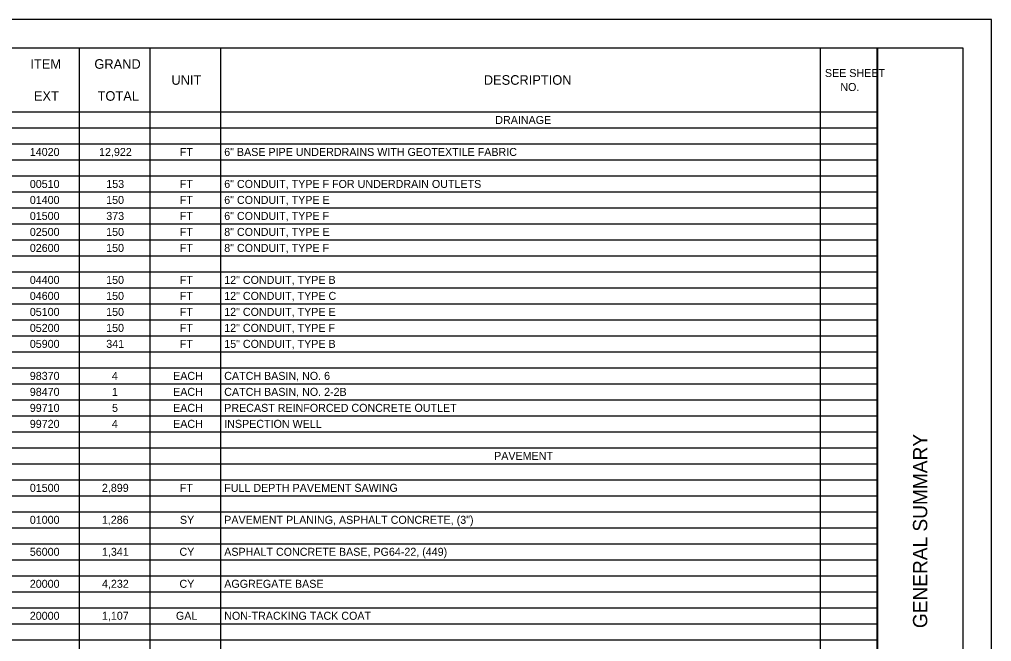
# Model space of a CAD drawing. Extents: x 0 to 34, y 0 to 22.
# Drawn here: x 16.99 to 34, y 11.11 to 22 of the extents above; entities that cross this region are included whole.
import ezdxf

# ---------------------------------------------------------------- set-up
doc = ezdxf.new("R2010")
doc.units = 0
for name, color, linetype in [('SH_Border', 7, 'Continuous'), ('SH_Cut_Line', 7, 'Continuous'), ('SH_Data', 7, 'Continuous'), ('SH_Text', 7, 'Continuous')]:
    doc.layers.add(name, color=color, linetype=linetype)

msp = doc.modelspace()

# ---------------------------------------------------------------- linework, layer by layer
at = {"layer": 'SH_Border'}
msp.add_line((32, 0.5), (32, 21.5), dxfattribs=at)
msp.add_lwpolyline([(1.5, 21.5), (33.5, 21.5), (33.5, 0.5), (1.5, 0.5)], close=True, dxfattribs=at)
at = {"layer": 'SH_Cut_Line'}
msp.add_lwpolyline([(0, 0), (34, 0), (34, 22), (0, 22)], close=True, dxfattribs=at)
at = {"layer": 'SH_Text'}
for p, q in [((1.5, 21.5), (32.004, 21.5)), ((18.036, 21.5), (18.036, 0.5)), ((19.272, 21.5), (19.272, 0.5)), ((20.507, 21.5), (20.507, 0.5)), ((30.999, 21.5), (30.999, 0.5)), ((32.004, 21.5), (32.004, 0.5)), ((1.5, 20.38), (32.004, 20.38)), ((1.5, 20.1), (32.004, 20.1)), ((1.5, 19.82), (32.004, 19.82)), ((1.5, 19.54), (32.004, 19.54)), ((1.5, 19.26), (32.004, 19.26)), ((1.5, 18.98), (32.004, 18.98)), ((1.5, 18.7), (32.004, 18.7)), ((1.5, 18.42), (32.004, 18.42)), ((1.5, 18.14), (32.004, 18.14)), ((1.5, 17.86), (32.004, 17.86)), ((1.5, 17.58), (32.004, 17.58)), ((1.5, 17.3), (32.004, 17.3)), ((1.5, 17.02), (32.004, 17.02)), ((1.5, 16.74), (32.004, 16.74)), ((1.5, 16.46), (32.004, 16.46)), ((1.5, 16.18), (32.004, 16.18)), ((1.5, 15.9), (32.004, 15.9)), ((1.5, 15.62), (32.004, 15.62)), ((1.5, 15.34), (32.004, 15.34)), ((1.5, 15.06), (32.004, 15.06)), ((1.5, 14.78), (32.004, 14.78)), ((1.5, 14.5), (32.004, 14.5)), ((1.5, 14.22), (32.004, 14.22)), ((1.5, 13.94), (32.004, 13.94)), ((1.5, 13.66), (32.004, 13.66)), ((1.5, 13.38), (32.004, 13.38)), ((1.5, 13.1), (32.004, 13.1)), ((1.5, 12.82), (32.004, 12.82)), ((1.5, 12.54), (32.004, 12.54)), ((1.5, 12.26), (32.004, 12.26)), ((1.5, 11.98), (32.004, 11.98)), ((1.5, 11.7), (32.004, 11.7)), ((1.5, 11.42), (32.004, 11.42)), ((1.5, 11.14), (32.004, 11.14))]:
    msp.add_line(p, q, dxfattribs=at)

# ---------------------------------------------------------------- texts
at = {"layer": 'SH_Data'}
msp.add_text('GENERAL SUMMARY', height=0.25, rotation=90, dxfattribs=at).set_placement((32.875, 11.344))
at = {"layer": 'SH_Text'}
for s, height, p in [('ITEM', 0.168, (17.181, 21.136)), ('GRAND', 0.168, (18.301, 21.136)), ('SEE SHEET ', 0.14, (31.084, 20.992)), ('UNIT', 0.168, (19.649, 20.856)), ('DESCRIPTION', 0.168, (25.115, 20.856)), ('NO.', 0.14, (31.354, 20.747)), ('EXT', 0.168, (17.242, 20.576)), ('TOTAL', 0.168, (18.357, 20.576)), ('DRAINAGE', 0.14, (25.316, 20.17)), ('14020', 0.14, (17.171, 19.61)), ('12,922', 0.14, (18.383, 19.61)), ('FT', 0.14, (19.796, 19.61)), ('6" BASE PIPE UNDERDRAINS WITH GEOTEXTILE FABRIC', 0.14, (20.573, 19.61)), ('00510', 0.14, (17.171, 19.05)), ('153', 0.14, (18.509, 19.05)), ('FT', 0.14, (19.796, 19.05)), ('6" CONDUIT, TYPE F FOR UNDERDRAIN OUTLETS', 0.14, (20.573, 19.05)), ('01400', 0.14, (17.171, 18.77)), ('150', 0.14, (18.507, 18.77)), ('FT', 0.14, (19.796, 18.77)), ('6" CONDUIT, TYPE E', 0.14, (20.573, 18.77)), ('01500', 0.14, (17.171, 18.49)), ('373', 0.14, (18.509, 18.49)), ('FT', 0.14, (19.796, 18.49)), ('6" CONDUIT, TYPE F', 0.14, (20.573, 18.49)), ('02500', 0.14, (17.171, 18.21)), ('150', 0.14, (18.507, 18.21)), ('FT', 0.14, (19.796, 18.21)), ('8" CONDUIT, TYPE E', 0.14, (20.573, 18.21)), ('02600', 0.14, (17.171, 17.93)), ('150', 0.14, (18.507, 17.93)), ('FT', 0.14, (19.796, 17.93)), ('8" CONDUIT, TYPE F', 0.14, (20.573, 17.93)), ('04400', 0.14, (17.171, 17.37)), ('150', 0.14, (18.507, 17.37)), ('FT', 0.14, (19.796, 17.37)), ('12" CONDUIT, TYPE B', 0.14, (20.573, 17.37)), ('04600', 0.14, (17.171, 17.09)), ('150', 0.14, (18.507, 17.09)), ('FT', 0.14, (19.796, 17.09)), ('12" CONDUIT, TYPE C', 0.14, (20.573, 17.09)), ('05100', 0.14, (17.171, 16.81)), ('150', 0.14, (18.507, 16.81)), ('FT', 0.14, (19.796, 16.81)), ('12" CONDUIT, TYPE E', 0.14, (20.573, 16.81)), ('05200', 0.14, (17.171, 16.53)), ('150', 0.14, (18.507, 16.53)), ('12" CONDUIT, TYPE F', 0.14, (20.573, 16.53)), ('FT', 0.14, (19.796, 16.53)), ('05900', 0.14, (17.171, 16.25)), ('341', 0.14, (18.509, 16.25)), ('FT', 0.14, (19.796, 16.25)), ('15" CONDUIT, TYPE B', 0.14, (20.573, 16.25)), ('98370', 0.14, (17.171, 15.69)), ('4', 0.14, (18.607, 15.69)), ('EACH', 0.14, (19.679, 15.69)), ('CATCH BASIN, NO. 6', 0.14, (20.573, 15.69)), ('98470', 0.14, (17.171, 15.41)), ('1', 0.14, (18.609, 15.41)), ('EACH', 0.14, (19.679, 15.41)), ('CATCH BASIN, NO. 2-2B', 0.14, (20.573, 15.41)), ('99710', 0.14, (17.171, 15.13)), ('5', 0.14, (18.61, 15.13)), ('EACH', 0.14, (19.679, 15.13)), ('PRECAST REINFORCED CONCRETE OUTLET', 0.14, (20.573, 15.13)), ('99720', 0.14, (17.171, 14.85)), ('4', 0.14, (18.607, 14.85)), ('EACH', 0.14, (19.679, 14.85)), ('INSPECTION WELL', 0.14, (20.573, 14.85)), ('PAVEMENT', 0.14, (25.296, 14.29)), ('01500', 0.14, (17.171, 13.73)), ('2,899', 0.14, (18.433, 13.73)), ('FT', 0.14, (19.796, 13.73)), ('FULL DEPTH PAVEMENT SAWING', 0.14, (20.573, 13.73)), ('01000', 0.14, (17.171, 13.17)), ('1,286', 0.14, (18.432, 13.17)), ('SY', 0.14, (19.798, 13.17)), ('PAVEMENT PLANING, ASPHALT CONCRETE, (3")', 0.14, (20.573, 13.17)), ('56000', 0.14, (17.171, 12.61)), ('1,341', 0.14, (18.434, 12.61)), ('CY', 0.14, (19.79, 12.61)), ('ASPHALT CONCRETE BASE, PG64-22, (449)', 0.14, (20.573, 12.61)), ('20000', 0.14, (17.171, 12.05)), ('4,232', 0.14, (18.434, 12.05)), ('CY', 0.14, (19.79, 12.05)), ('AGGREGATE BASE', 0.14, (20.573, 12.05)), ('20000', 0.14, (17.171, 11.49)), ('1,107', 0.14, (18.433, 11.49)), ('GAL', 0.14, (19.728, 11.49)), ('NON-TRACKING TACK COAT', 0.14, (20.573, 11.49))]:
    msp.add_text(s, height=height, dxfattribs=at).set_placement(p)

doc.saveas('drawing.dxf')
